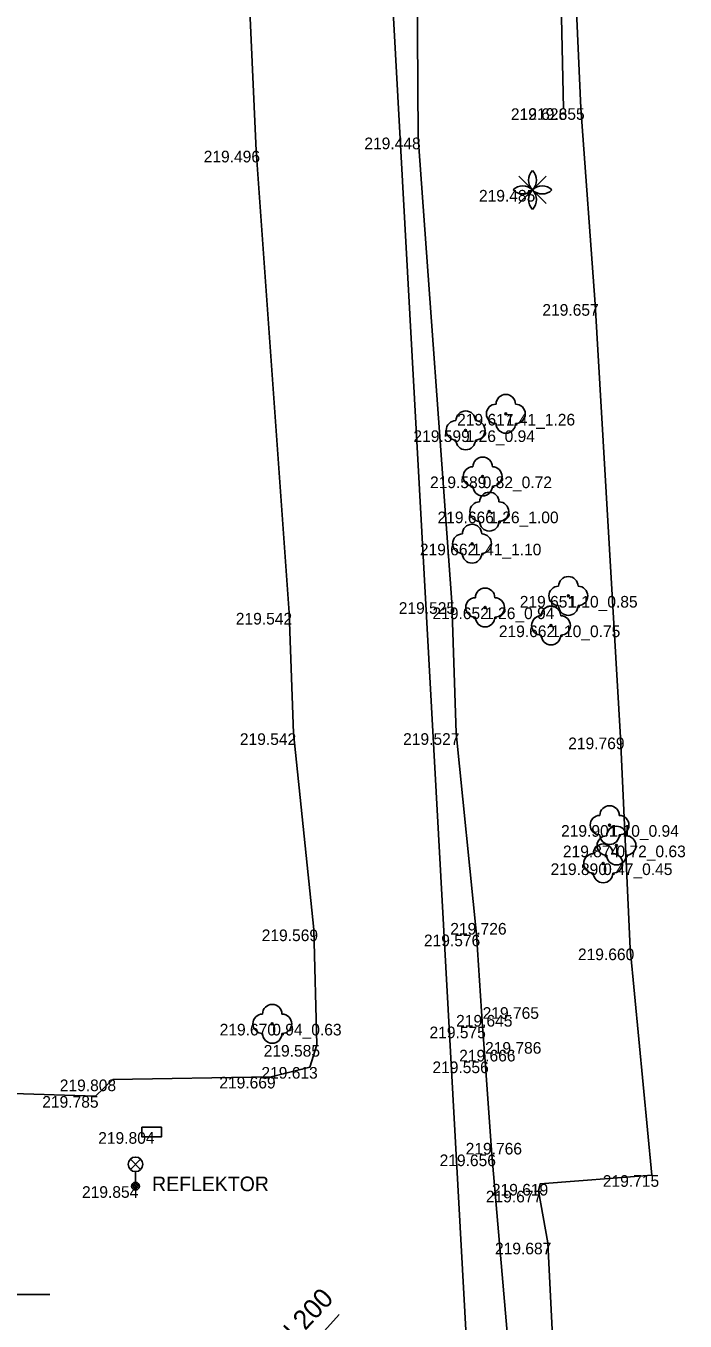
# Model space of a CAD drawing. Extents: x -599516 to -599132, y -1163668 to -1163119.
# Drawn here: x -599237.12 to -599220.15, y -1163560.2 to -1163526.85 of the extents above; entities that cross this region are included whole.
import ezdxf

# ---------------------------------------------------------------- set-up
doc = ezdxf.new("R2010")
doc.units = 0
for name, color, linetype in [('_ZEMERENI OBLAST', 7, 'Continuous'), ('Bod-oznac1', 7, 'Continuous'), ('Bod-oznac2', 7, 'Continuous'), ('Bod-oznac3', 7, 'Continuous'), ('Bod-vyska1', 7, 'Continuous'), ('Bod-vyska2', 7, 'Continuous'), ('Bod-vyska3', 7, 'Continuous'), ('Z_cela-hrobu-horni-linie', 7, 'Continuous'), ('Z_elektro-silno-znacky-lampa', 7, 'Continuous'), ('Z_elektro-silno-znacky-rozdel-skrin', 7, 'Continuous'), ('Z_kanalizace-destova', 7, 'Continuous'), ('Z_komunikace', 7, 'Continuous'), ('Z_obvod-kmene-spodek-ve-vysce1_2m', 7, 'Continuous'), ('Z_ploty-drateny-kovovy', 7, 'Continuous'), ('Z_stromy-kere', 7, 'Continuous'), ('Z_vol-txt-popis-objektu', 7, 'Continuous'), ('Z_zdi-ohradni', 7, 'Continuous'), ('Z_zelen-obvod', 7, 'Continuous')]:
    doc.layers.add(name, color=color, linetype=linetype)

msp = doc.modelspace()

# ---------------------------------------------------------------- linework, layer by layer
at = {"layer": '_ZEMERENI OBLAST'}
msp.add_lwpolyline([(-599220.632, -1163654.171), (-599229.344, -1163496.11), (-599224.438, -1163495.846), (-599230.06, -1163390.87)], dxfattribs=at)
at = {"layer": 'Bod-oznac1'}
for p, q in [((-599223.28, -1163528.969), (-599223.28, -1163528.969)), ((-599222.83, -1163528.965), (-599222.83, -1163528.965)), ((-599227.019, -1163529.722), (-599227.019, -1163529.722)), ((-599231.19, -1163530.061), (-599231.19, -1163530.061)), ((-599224.079, -1163531.07), (-599224.079, -1163531.07)), ((-599222.467, -1163534.01), (-599222.467, -1163534.01)), ((-599224.766, -1163536.837), (-599224.766, -1163536.837)), ((-599225.8, -1163537.262), (-599225.8, -1163537.262)), ((-599225.362, -1163538.45), (-599225.362, -1163538.45)), ((-599225.191, -1163539.354), (-599225.191, -1163539.354)), ((-599225.635, -1163540.181), (-599225.635, -1163540.181)), ((-599223.156, -1163541.526), (-599223.156, -1163541.526)), ((-599226.156, -1163541.688), (-599226.156, -1163541.688)), ((-599225.299, -1163541.823), (-599225.299, -1163541.823)), ((-599230.34, -1163541.962), (-599230.34, -1163541.962)), ((-599223.602, -1163542.287), (-599223.602, -1163542.287)), ((-599230.235, -1163545.064), (-599230.235, -1163545.064)), ((-599226.042, -1163545.061), (-599226.042, -1163545.061)), ((-599221.813, -1163545.173), (-599221.813, -1163545.173)), ((-599222.094, -1163547.428), (-599222.094, -1163547.428)), ((-599221.916, -1163547.955), (-599221.916, -1163547.955)), ((-599222.259, -1163548.414), (-599222.259, -1163548.414)), ((-599229.707, -1163550.116), (-599229.707, -1163550.116)), ((-599225.517, -1163550.248), (-599225.517, -1163550.248)), ((-599221.566, -1163550.606), (-599221.566, -1163550.606)), ((-599230.779, -1163552.545), (-599230.779, -1163552.545)), ((-599225.362, -1163552.617), (-599225.362, -1163552.617)), ((-599229.634, -1163553.091), (-599229.634, -1163553.091)), ((-599225.3, -1163553.515), (-599225.3, -1163553.515)), ((-599230.811, -1163553.91), (-599230.811, -1163553.91)), ((-599229.808, -1163553.658), (-599229.808, -1163553.658)), ((-599234.887, -1163553.98), (-599234.887, -1163553.98)), ((-599235.334, -1163554.406), (-599235.334, -1163554.406)), ((-599233.885, -1163555.335), (-599233.885, -1163555.335)), ((-599225.126, -1163555.911), (-599225.126, -1163555.911)), ((-599221.003, -1163556.443), (-599221.003, -1163556.443)), ((-599234.301, -1163556.727), (-599234.301, -1163556.727)), ((-599223.921, -1163556.844), (-599223.921, -1163556.844)), ((-599223.884, -1163556.668), (-599223.884, -1163556.668)), ((-599223.687, -1163558.182), (-599223.687, -1163558.182))]:
    msp.add_line(p, q, dxfattribs=at)
at = {"layer": 'Bod-oznac2'}
for p, q in [((-599225.517, -1163550.248), (-599225.517, -1163550.248)), ((-599225.362, -1163552.617), (-599225.362, -1163552.617)), ((-599225.3, -1163553.515), (-599225.3, -1163553.515)), ((-599225.126, -1163555.911), (-599225.126, -1163555.911))]:
    msp.add_line(p, q, dxfattribs=at)
at = {"layer": 'Bod-oznac3'}
for p, q in [((-599225.362, -1163552.617), (-599225.362, -1163552.617)), ((-599225.3, -1163553.515), (-599225.3, -1163553.515))]:
    msp.add_line(p, q, dxfattribs=at)
at = {"layer": 'Z_cela-hrobu-horni-linie'}
msp.add_lwpolyline([(-599225.517, -1163550.248), (-599225.362, -1163552.617), (-599225.362, -1163552.617), (-599225.3, -1163553.515), (-599225.3, -1163553.515), (-599225.126, -1163555.911)], dxfattribs=at)
at = {"layer": 'Z_elektro-silno-znacky-lampa'}
for p, q in [((-599234.434, -1163556.297), (-599234.169, -1163556.032)), ((-599234.434, -1163556.032), (-599234.169, -1163556.297)), ((-599234.301, -1163556.352), (-599234.301, -1163556.627))]:
    msp.add_line(p, q, dxfattribs=at)
for centre, radius in [((-599234.301, -1163556.164), 0.188), ((-599234.301, -1163556.727), 0.1), ((-599234.301, -1163556.727), 0.065), ((-599234.301, -1163556.727), 0.03)]:
    msp.add_circle(centre, radius, dxfattribs=at)
at = {"layer": 'Z_elektro-silno-znacky-rozdel-skrin'}
msp.add_lwpolyline([(-599234.135, -1163555.21), (-599233.635, -1163555.21), (-599233.635, -1163555.46), (-599234.135, -1163555.46)], close=True, dxfattribs=at)
at = {"layer": 'Z_kanalizace-destova'}
for p, q in [((-599245.056, -1163559.532), (-599236.511, -1163559.515)), ((-599231.303, -1163562.533), (-599229.06, -1163560.028))]:
    msp.add_line(p, q, dxfattribs=at)
at = {"layer": 'Z_komunikace'}
msp.add_line((-599226.156, -1163541.688), (-599226.042, -1163545.061), dxfattribs=at)
for points in [[(-599243.538, -1163474.658), (-599243.723, -1163474.972), (-599243.67, -1163475.664), (-599243.639, -1163476.428), (-599243.4, -1163481.411), (-599243.381, -1163489.225), (-599243.346, -1163490.493), (-599242.699, -1163490.784), (-599242.282, -1163490.76), (-599236.651, -1163490.572), (-599235.413, -1163490.641), (-599233.862, -1163491.132), (-599232.873, -1163491.765), (-599231.684, -1163492.382), (-599230.881, -1163493.069), (-599229.898, -1163494.138), (-599229.174, -1163495.502), (-599228.7, -1163499.092), (-599228.046, -1163504.018), (-599227.508, -1163512.042), (-599227.073, -1163521.662), (-599227.019, -1163529.722), (-599226.156, -1163541.688)], [(-599242.352, -1163496.199), (-599238.673, -1163496.152), (-599233.22, -1163495.694), (-599233.036, -1163496.951), (-599232.478, -1163501.544), (-599232.003, -1163512.222), (-599231.555, -1163522.067), (-599231.19, -1163530.061), (-599230.34, -1163541.962)], [(-599230.34, -1163541.962), (-599230.235, -1163545.064), (-599229.707, -1163550.116), (-599229.634, -1163553.091), (-599229.808, -1163553.658), (-599230.811, -1163553.91), (-599234.887, -1163553.98), (-599235.334, -1163554.406), (-599237.721, -1163554.332), (-599238.967, -1163554.109)], [(-599226.042, -1163545.061), (-599225.517, -1163550.248), (-599225.362, -1163552.617), (-599225.3, -1163553.515), (-599225.126, -1163555.911), (-599224.729, -1163560.492), (-599227.443, -1163560.784)]]:
    msp.add_lwpolyline(points, dxfattribs=at)
at = {"layer": 'Z_ploty-drateny-kovovy'}
msp.add_lwpolyline([(-599223.921, -1163556.844), (-599223.687, -1163558.182), (-599223.283, -1163566.268), (-599222.929, -1163572.869), (-599222.817, -1163576.324)], dxfattribs=at)
at = {"layer": 'Z_stromy-kere'}
for p, q in [((-599223.725, -1163530.716), (-599224.433, -1163531.424)), ((-599224.433, -1163530.716), (-599223.725, -1163531.424)), ((-599223.725, -1163530.716), (-599224.433, -1163531.424)), ((-599224.433, -1163530.716), (-599223.725, -1163531.424)), ((-599223.725, -1163530.716), (-599224.433, -1163531.424)), ((-599224.433, -1163530.716), (-599223.725, -1163531.424))]:
    msp.add_line(p, q, dxfattribs=at)
for centre in [(-599224.766, -1163536.837), (-599225.8, -1163537.262), (-599225.362, -1163538.45), (-599225.191, -1163539.354), (-599225.635, -1163540.181), (-599223.156, -1163541.526), (-599225.299, -1163541.823), (-599223.602, -1163542.287), (-599222.094, -1163547.428), (-599221.916, -1163547.955), (-599222.259, -1163548.414), (-599230.779, -1163552.545)]:
    msp.add_circle(centre, 0.025, dxfattribs=at)
for centre, radius, start, end in [((-599224.329, -1163530.82), 0.354, 225, 45), ((-599224.329, -1163530.82), 0.354, 225, 45), ((-599224.329, -1163530.82), 0.354, 225, 45), ((-599223.829, -1163530.82), 0.354, 135, 315), ((-599223.829, -1163530.82), 0.354, 135, 315), ((-599223.829, -1163530.82), 0.354, 135, 315), ((-599224.329, -1163531.32), 0.354, 315, 135), ((-599224.329, -1163531.32), 0.354, 315, 135), ((-599224.329, -1163531.32), 0.354, 315, 135), ((-599223.829, -1163531.32), 0.354, 45, 225), ((-599223.829, -1163531.32), 0.354, 45, 225), ((-599223.829, -1163531.32), 0.354, 45, 225), ((-599225.016, -1163536.837), 0.25, 90, 270), ((-599224.766, -1163536.587), 0.25, 0, 180), ((-599224.516, -1163536.837), 0.25, 270, 90), ((-599225.8, -1163537.012), 0.25, 0, 180), ((-599226.05, -1163537.262), 0.25, 90, 270), ((-599225.55, -1163537.262), 0.25, 270, 90), ((-599224.766, -1163537.087), 0.25, 180, 0), ((-599225.8, -1163537.512), 0.25, 180, 0), ((-599225.362, -1163538.2), 0.25, 0, 180), ((-599225.612, -1163538.45), 0.25, 90, 270), ((-599225.112, -1163538.45), 0.25, 270, 90), ((-599225.362, -1163538.7), 0.25, 180, 0), ((-599225.191, -1163539.104), 0.25, 0, 180), ((-599225.441, -1163539.354), 0.25, 90, 270), ((-599224.941, -1163539.354), 0.25, 270, 90), ((-599225.191, -1163539.604), 0.25, 180, 0), ((-599225.885, -1163540.181), 0.25, 90, 270), ((-599225.635, -1163539.931), 0.25, 0, 180), ((-599225.385, -1163540.181), 0.25, 270, 90), ((-599225.635, -1163540.431), 0.25, 180, 0), ((-599223.406, -1163541.526), 0.25, 90, 270), ((-599223.156, -1163541.276), 0.25, 0, 180), ((-599222.906, -1163541.526), 0.25, 270, 90), ((-599225.549, -1163541.823), 0.25, 90, 270), ((-599225.299, -1163541.573), 0.25, 0, 180), ((-599225.049, -1163541.823), 0.25, 270, 90), ((-599223.602, -1163542.037), 0.25, 0, 180), ((-599223.156, -1163541.776), 0.25, 180, 0), ((-599225.299, -1163542.073), 0.25, 180, 0), ((-599223.852, -1163542.287), 0.25, 90, 270), ((-599223.352, -1163542.287), 0.25, 270, 90), ((-599223.602, -1163542.537), 0.25, 180, 0), ((-599222.094, -1163547.178), 0.25, 0, 180), ((-599222.344, -1163547.428), 0.25, 90, 270), ((-599221.844, -1163547.428), 0.25, 270, 90), ((-599221.916, -1163547.705), 0.25, 0, 180), ((-599222.259, -1163548.164), 0.25, 0, 180), ((-599222.166, -1163547.955), 0.25, 90, 270), ((-599222.094, -1163547.678), 0.25, 180, 0), ((-599221.666, -1163547.955), 0.25, 270, 90), ((-599222.509, -1163548.414), 0.25, 90, 270), ((-599221.916, -1163548.205), 0.25, 180, 0), ((-599222.009, -1163548.414), 0.25, 270, 90), ((-599222.259, -1163548.664), 0.25, 180, 0), ((-599231.029, -1163552.545), 0.25, 90, 270), ((-599230.779, -1163552.295), 0.25, 0, 180), ((-599230.529, -1163552.545), 0.25, 270, 90), ((-599230.779, -1163552.795), 0.25, 180, 0)]:
    msp.add_arc(centre, radius, start, end, dxfattribs=at)
at = {"layer": 'Z_zdi-ohradni'}
msp.add_line((-599221.813, -1163545.173), (-599221.566, -1163550.606), dxfattribs=at)
for points in [[(-599223.572, -1163512.402), (-599222.83, -1163528.965), (-599222.467, -1163534.01), (-599221.813, -1163545.173)], [(-599221.566, -1163550.606), (-599221.003, -1163556.443), (-599223.884, -1163556.668), (-599223.921, -1163556.844)]]:
    msp.add_lwpolyline(points, dxfattribs=at)
at = {"layer": 'Z_zelen-obvod'}
msp.add_lwpolyline([(-599224.034, -1163512.652), (-599223.436, -1163521.933), (-599223.28, -1163528.969)], dxfattribs=at)

# ---------------------------------------------------------------- texts
at = {"layer": 'Bod-vyska1'}
for s, p in [('219.628', (-599224.635, -1163529.269)), ('219.655', (-599224.185, -1163529.265)), ('219.448', (-599228.408, -1163530.022)), ('219.496', (-599232.545, -1163530.361)), ('219.485', (-599225.457, -1163531.37)), ('219.657', (-599223.824, -1163534.31)), ('219.617', (-599226.019, -1163537.137)), ('219.599', (-599227.144, -1163537.562)), ('219.589', (-599226.717, -1163538.75)), ('219.666', (-599226.523, -1163539.654)), ('219.662', (-599226.978, -1163540.481)), ('219.651', (-599224.407, -1163541.826)), ('219.542', (-599231.718, -1163542.262)), ('219.525', (-599227.522, -1163541.988)), ('219.652', (-599226.654, -1163542.123)), ('219.662', (-599224.945, -1163542.587)), ('219.542', (-599231.613, -1163545.364)), ('219.527', (-599227.41, -1163545.361)), ('219.769', (-599223.158, -1163545.473)), ('219.901', (-599223.343, -1163547.728)), ('219.874', (-599223.295, -1163548.255)), ('219.890', (-599223.612, -1163548.714)), ('219.569', (-599231.051, -1163550.416)), ('219.576', (-599226.874, -1163550.548)), ('219.660', (-599222.908, -1163550.906)), ('219.670', (-599232.134, -1163552.845)), ('219.575', (-599226.73, -1163552.917)), ('219.585', (-599231, -1163553.391)), ('219.556', (-599226.655, -1163553.815)), ('219.669', (-599232.143, -1163554.21)), ('219.613', (-599231.059, -1163553.958)), ('219.808', (-599236.251, -1163554.28)), ('219.785', (-599236.702, -1163554.706)), ('219.804', (-599235.261, -1163555.635)), ('219.656', (-599226.47, -1163556.211)), ('219.715', (-599222.267, -1163556.743)), ('219.854', (-599235.679, -1163557.027)), ('219.677', (-599225.28, -1163557.144)), ('219.619', (-599225.124, -1163556.968)), ('219.687', (-599225.044, -1163558.482))]:
    msp.add_text(s, height=0.3, dxfattribs=at).set_placement(p)
at = {"layer": 'Bod-vyska2'}
for s, p in [('219.726', (-599226.195, -1163550.248)), ('219.645', (-599226.045, -1163552.617)), ('219.666', (-599225.966, -1163553.515)), ('219.766', (-599225.799, -1163555.911))]:
    msp.add_text(s, height=0.3, dxfattribs=at).set_placement(p)
at = {"layer": 'Bod-vyska3'}
for s, p in [('219.765', (-599225.362, -1163552.417)), ('219.786', (-599225.3, -1163553.315))]:
    msp.add_text(s, height=0.3, dxfattribs=at).set_placement(p)
at = {"layer": 'Z_kanalizace-destova'}
msp.add_text('DN 200', height=0.5, rotation=46.8539, dxfattribs=at).set_placement((-599230.721, -1163561.301))
at = {"layer": 'Z_obvod-kmene-spodek-ve-vysce1_2m'}
for s, p in [('1.41_1.26', (-599224.766, -1163537.137)), ('1.26_0.94', (-599225.8, -1163537.562)), ('0.82_0.72', (-599225.362, -1163538.75)), ('1.26_1.00', (-599225.191, -1163539.654)), ('1.41_1.10', (-599225.635, -1163540.481)), ('1.10_0.85', (-599223.156, -1163541.826)), ('1.26_0.94', (-599225.299, -1163542.123)), ('1.10_0.75', (-599223.602, -1163542.587)), ('1.10_0.94', (-599222.094, -1163547.728)), ('0.72_0.63', (-599221.916, -1163548.255)), ('0.47_0.45', (-599222.259, -1163548.714)), ('0.94_0.63', (-599230.779, -1163552.845))]:
    msp.add_text(s, height=0.3, dxfattribs=at).set_placement(p)
at = {"layer": 'Z_vol-txt-popis-objektu'}
msp.add_text('REFLEKTOR', height=0.375, dxfattribs=at).set_placement((-599233.875, -1163556.855))

doc.saveas('drawing.dxf')
